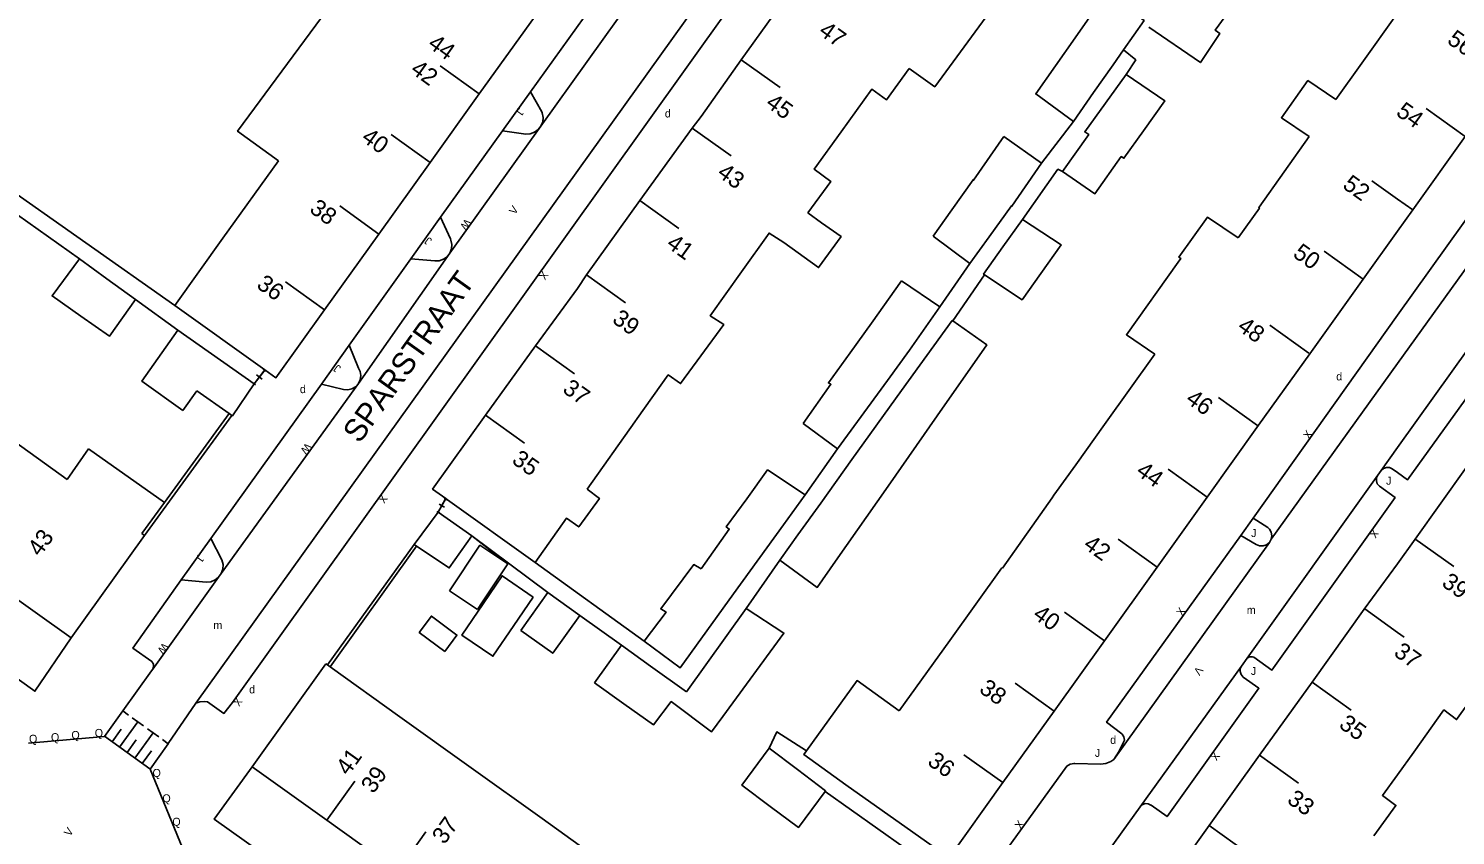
# Model space of a CAD drawing. Extents: x 134999 to 136502, y 457398 to 459002.
# Drawn here: x 135414.5 to 135503.6, y 457448.2 to 457498.6 of the extents above; entities that cross this region are included whole.
import ezdxf

# ---------------------------------------------------------------- set-up
doc = ezdxf.new("R2010")
doc.units = 0
for name, color, linetype in [('RI_DGTB_15', 7, 'Continuous'), ('RI_DGTB_23', 7, 'Continuous'), ('RI_DGTB_29', 7, 'Continuous'), ('RI_DGTB_30', 7, 'Continuous'), ('RI_DGTB_31', 7, 'Continuous'), ('RI_DGTB_35', 7, 'Continuous'), ('RI_DGTB_36', 7, 'Continuous'), ('RI_DGTB_37', 7, 'Continuous'), ('RI_DGTB_4', 7, 'Continuous'), ('RI_DGTB_43', 7, 'Continuous'), ('RI_DGTB_48', 7, 'Continuous'), ('RI_DGTB_5', 7, 'Continuous'), ('RI_DGTB_53', 7, 'Continuous'), ('RI_DGTB_54', 7, 'Continuous'), ('RI_DGTB_6', 7, 'Continuous')]:
    doc.layers.add(name, color=color, linetype=linetype)

msp = doc.modelspace()

# ---------------------------------------------------------------- linework, layer by layer
at = {"layer": 'RI_DGTB_15'}
for p, q in [((135459.001, 457496.658), (135461.441, 457494.913)), ((135442.64, 457494.517), (135440.202, 457496.264)), ((135504.228, 457491.852), (135501.788, 457493.597)), ((135439.569, 457490.229), (135437.131, 457491.976)), ((135455.93, 457492.383), (135458.37, 457490.638)), ((135500, 457487.937), (135498.402, 457489.08)), ((135436.357, 457485.745), (135433.935, 457487.513)), ((135452.672, 457487.848), (135455.112, 457486.103)), ((135500.945, 457487.267), (135500, 457487.937)), ((135497.85, 457482.939), (135495.41, 457484.685)), ((135449.335, 457483.202), (135451.775, 457481.457)), ((135432.978, 457481.028), (135430.54, 457482.775)), ((135494.459, 457478.309), (135492.019, 457480.055)), ((135446.151, 457478.77), (135448.591, 457477.025)), ((135491.259, 457473.796), (135488.819, 457475.542)), ((135443.034, 457474.431), (135445.474, 457472.686)), ((135488.113, 457469.317), (135485.673, 457471.063)), ((135484.978, 457464.931), (135482.538, 457466.677)), ((135501.079, 457466.713), (135503.522, 457464.972)), ((135481.696, 457460.341), (135479.193, 457462.132)), ((135497.957, 457462.329), (135500, 457460.862)), ((135500, 457460.862), (135500.412, 457460.56)), ((135478.547, 457455.936), (135476.107, 457457.682)), ((135494.658, 457457.756), (135497.095, 457456.006)), ((135475.354, 457451.47), (135472.914, 457453.216)), ((135491.382, 457453.187), (135493.819, 457451.437)), ((135433.115, 457449.117), (135434.86, 457451.558)), ((135437.555, 457445.942), (135439.3, 457448.383)), ((135488.229, 457448.789), (135490.666, 457447.039))]:
    msp.add_line(p, q, dxfattribs=at)
at = {"layer": 'RI_DGTB_23'}
msp.add_line((135428.572, 457476.401), (135429.243, 457477.27), dxfattribs=at)
at = {"layer": 'RI_DGTB_31'}
for p, q in [((135420.373, 457455.949), (135420.727, 457455.693)), ((135420.963, 457455.523), (135421.671, 457455.011)), ((135419.702, 457454.027), (135420.273, 457454.817)), ((135420.174, 457453.686), (135421.317, 457455.267)), ((135421.117, 457453.003), (135422.26, 457454.584)), ((135421.906, 457454.84), (135422.614, 457454.328)), ((135419.23, 457454.368), (135422.061, 457452.321)), ((135420.645, 457453.345), (135421.217, 457454.135)), ((135422.85, 457454.158), (135423.204, 457453.902)), ((135421.589, 457452.662), (135422.161, 457453.453))]:
    msp.add_line(p, q, dxfattribs=at)
at = {"layer": 'RI_DGTB_4'}
for p, q in [((135459.001, 457496.658), (135462.228, 457501.151)), ((135446.129, 457499.387), (135442.64, 457494.517)), ((135439.569, 457490.229), (135442.64, 457494.517)), ((135452.672, 457487.848), (135455.93, 457492.383)), ((135504.228, 457491.852), (135500.945, 457487.267)), ((135436.357, 457485.745), (135439.569, 457490.229)), ((135449.335, 457483.202), (135452.672, 457487.848)), ((135500.945, 457487.267), (135500, 457485.946)), ((135432.978, 457481.028), (135436.357, 457485.745)), ((135500, 457485.946), (135497.85, 457482.939)), ((135497.85, 457482.939), (135494.513, 457478.27)), ((135423.623, 457481.289), (135429.243, 457477.27)), ((135443.034, 457474.431), (135446.151, 457478.77)), ((135494.513, 457478.27), (135491.321, 457473.805)), ((135491.321, 457473.805), (135488.113, 457469.317)), ((135422.974, 457468.984), (135418.233, 457472.329)), ((135501.103, 457466.696), (135504.31, 457471.196)), ((135422.974, 457468.984), (135421.562, 457467.037)), ((135488.113, 457469.317), (135484.978, 457464.931)), ((135421.562, 457467.037), (135421.724, 457466.92)), ((135417.141, 457460.514), (135421.724, 457466.92)), ((135500, 457465.15), (135501.103, 457466.696)), ((135484.978, 457464.931), (135481.696, 457460.341)), ((135497.921, 457462.308), (135500, 457465.15)), ((135412.26, 457464.007), (135417.141, 457460.514)), ((135494.658, 457457.756), (135497.921, 457462.308)), ((135481.696, 457460.341), (135478.547, 457455.936)), ((135433.064, 457458.886), (135428.447, 457452.454)), ((135491.382, 457453.187), (135494.658, 457457.756)), ((135478.547, 457455.936), (135475.354, 457451.47)), ((135488.229, 457448.789), (135491.382, 457453.187)), ((135428.447, 457452.454), (135433.115, 457449.117)), ((135433.115, 457449.117), (135437.555, 457445.942)), ((135485.025, 457444.32), (135488.229, 457448.789))]:
    msp.add_line(p, q, dxfattribs=at)
for points in [[(135459.001, 457496.658), (135456.491, 457493.108), (135455.93, 457492.383)], [(135446.151, 457478.77), (135448.769, 457482.362), (135449.335, 457483.202)], [(135429.243, 457477.27), (135429.933, 457476.777), (135432.978, 457481.028)], [(135440.547, 457469.228), (135439.721, 457469.819), (135443.034, 457474.431)], [(135440.649, 457469.155), (135440.547, 457469.228)], [(135446.125, 457465.234), (135440.649, 457469.155)], [(135465.542, 457451.338), (135471.987, 457446.759)], [(135471.987, 457446.759), (135475.354, 457451.47)]]:
    msp.add_lwpolyline(points, dxfattribs=at)
at = {"layer": 'RI_DGTB_48'}
for p, q in [((135428.572, 457476.401), (135429.243, 457477.27)), ((135428.572, 457476.401), (135429.235, 457477.26)), ((135429.075, 457476.698), (135428.732, 457476.963)), ((135429.321, 457477.194), (135429.149, 457477.326)), ((135428.658, 457476.335), (135428.486, 457476.467)), ((135440.079, 457468.371), (135440.547, 457469.228)), ((135440.079, 457468.371), (135440.531, 457469.198)), ((135440.47, 457468.694), (135440.14, 457468.875)), ((135440.614, 457469.153), (135440.448, 457469.243)), ((135440.162, 457468.326), (135439.996, 457468.416))]:
    msp.add_line(p, q, dxfattribs=at)
at = {"layer": 'RI_DGTB_5'}
for p, q in [((135500, 457499.566), (135497.771, 457496.449)), ((135497.771, 457496.449), (135496.14, 457494.169)), ((135494.486, 457491.848), (135491.348, 457487.445)), ((135426.63, 457485.491), (135430.097, 457490.337)), ((135423.623, 457481.289), (135426.63, 457485.491)), ((135484.84, 457478.256), (135481.697, 457473.86)), ((135452.361, 457474.014), (135452.511, 457474.225)), ((135412.628, 457473.48), (135416.894, 457470.424)), ((135449.373, 457469.804), (135452.361, 457474.014)), ((135481.697, 457473.86), (135479.894, 457471.338)), ((135416.894, 457470.424), (135418.233, 457472.329)), ((135479.894, 457471.338), (135478.54, 457469.445)), ((135478.418, 457469.275), (135475.319, 457464.868)), ((135478.54, 457469.445), (135478.418, 457469.275)), ((135472.028, 457460.361), (135468.865, 457455.961)), ((135433.064, 457458.886), (135433.163, 457458.832)), ((135433.163, 457458.832), (135433.326, 457458.715)), ((135433.326, 457458.715), (135437.681, 457455.591)), ((135437.681, 457455.591), (135442.134, 457452.397)), ((135501.011, 457453.375), (135500, 457451.96)), ((135446.56, 457449.221), (135442.134, 457452.397)), ((135451.135, 457445.939), (135446.56, 457449.221))]:
    msp.add_line(p, q, dxfattribs=at)
for points in [[(135471.691, 457501.15), (135474.306, 457499.335), (135471.088, 457494.967), (135469.497, 457496.098)], [(135433.856, 457500.753), (135430.67, 457496.428)], [(135430.67, 457496.428), (135427.543, 457492.184), (135430.097, 457490.337)], [(135465.248, 457492.15), (135467.155, 457494.812), (135468.081, 457494.151), (135469.497, 457496.098)], [(135496.14, 457494.169), (135494.404, 457495.352), (135492.749, 457493.03), (135494.486, 457491.848)], [(135465.248, 457492.15), (135463.569, 457489.806), (135464.599, 457489.051), (135463.16, 457487.087)], [(135491.348, 457487.445), (135491.325, 457487.413), (135491.368, 457487.385), (135490.035, 457485.521)], [(135463.16, 457487.087), (135464.019, 457486.457)], [(135490.035, 457485.521), (135488.133, 457486.816), (135486.339, 457484.307), (135486.463, 457484.222), (135486.303, 457483.998)], [(135459.016, 457483.392), (135460.739, 457485.821), (135461.671, 457485.231)], [(135461.671, 457485.231), (135463.834, 457483.662), (135465.24, 457485.601), (135464.019, 457486.457)], [(135486.303, 457483.998), (135483.063, 457479.467), (135484.84, 457478.256)], [(135459.016, 457483.392), (135457.07, 457480.649), (135457.908, 457480.104), (135456.486, 457478.151)], [(135452.511, 457474.225), (135454.447, 457476.953), (135455.218, 457476.41), (135456.486, 457478.151)], [(135446.125, 457465.234), (135448.087, 457467.991), (135448.857, 457467.45), (135450.148, 457469.238), (135449.373, 457469.804)], [(135472.028, 457460.361), (135475.285, 457464.892), (135475.319, 457464.868)], [(135463.089, 457453.464), (135466.24, 457457.848), (135468.865, 457455.961)], [(135501.011, 457453.375), (135502.898, 457456.015), (135503.689, 457455.414), (135504.985, 457457.229)], [(135465.542, 457451.338), (135462.917, 457453.225), (135463.089, 457453.464)], [(135500, 457451.96), (135499.054, 457450.673), (135499.902, 457450.04), (135498.524, 457448.136)]]:
    msp.add_lwpolyline(points, dxfattribs=at)
at = {"layer": 'RI_DGTB_53'}
for p, q in [((135446.495, 457492.508), (135454.75, 457504.049)), ((135445.841, 457494.655), (135444.098, 457492.208)), ((135500, 457477.662), (135510.887, 457492.825)), ((135444.098, 457492.208), (135440.221, 457486.824)), ((135440.796, 457484.565), (135446.495, 457492.508)), ((135440.221, 457486.824), (135438.375, 457484.213)), ((135509.439, 457485.634), (135500, 457472.409)), ((135438.375, 457484.213), (135434.52, 457478.808)), ((135435.092, 457476.411), (135440.796, 457484.565)), ((135434.52, 457478.808), (135432.783, 457476.38)), ((135492.114, 457466.678), (135500, 457477.662)), ((135432.783, 457476.38), (135425.87, 457466.727)), ((135426.524, 457464.549), (135435.092, 457476.411)), ((135498.975, 457470.973), (135500, 457472.409)), ((135490.599, 457459.244), (135498.766, 457470.678)), ((135425.87, 457466.727), (135424.028, 457464.145)), ((135482.281, 457452.917), (135491.999, 457466.483)), ((135422.243, 457458.552), (135426.36, 457464.315)), ((135426.36, 457464.315), (135426.524, 457464.549)), ((135422.175, 457458.457), (135422.243, 457458.552)), ((135483.914, 457449.95), (135490.252, 457458.756))]:
    msp.add_line(p, q, dxfattribs=at)
for points in [[(135445.841, 457494.655), (135453.025, 457504.677), (135454.05, 457503.897), (135454.259, 457503.842), (135454.473, 457503.866), (135454.665, 457503.966), (135454.75, 457504.049)], [(135424.927, 457456.431), (135458.449, 457503.225)], [(135445.841, 457494.655), (135446.552, 457493.398), (135446.577, 457493.331), (135446.628, 457493.052), (135446.6, 457492.77), (135446.495, 457492.508)], [(135444.098, 457492.208), (135445.541, 457492.007), (135445.824, 457492.024), (135446.09, 457492.119), (135446.32, 457492.285), (135446.495, 457492.508)], [(135440.221, 457486.824), (135440.833, 457485.452), (135440.865, 457485.374), (135440.921, 457485.102), (135440.897, 457484.825), (135440.796, 457484.565)], [(135438.375, 457484.213), (135439.86, 457484.076), (135440.138, 457484.09), (135440.4, 457484.183), (135440.626, 457484.345), (135440.796, 457484.565)], [(135434.52, 457478.808), (135435.101, 457477.376), (135435.198, 457477.173), (135435.241, 457476.912), (135435.205, 457476.65), (135435.092, 457476.411)], [(135432.783, 457476.38), (135434.164, 457476.045), (135434.428, 457476.025), (135434.685, 457476.083), (135434.914, 457476.216), (135435.092, 457476.411)], [(135425.87, 457466.727), (135426.568, 457465.386), (135426.633, 457465.105), (135426.618, 457464.819), (135426.524, 457464.549)], [(135424.028, 457464.145), (135425.59, 457463.989), (135425.874, 457464.023), (135426.137, 457464.135), (135426.36, 457464.315)], [(135424.028, 457464.145), (135421, 457459.868), (135422.19, 457459.039), (135422.281, 457458.881), (135422.297, 457458.701), (135422.243, 457458.552)], [(135422.175, 457458.457), (135420.37, 457455.951)], [(135422.175, 457458.457), (135422.235, 457458.53), (135422.243, 457458.552)], [(135424.927, 457456.431), (135423.215, 457453.917), (135423.203, 457453.899)], [(135427.22, 457456.487), (135426.691, 457455.799), (135425.655, 457456.509), (135425.475, 457456.541), (135425.193, 457456.525), (135424.927, 457456.431)], [(135420.37, 457455.951), (135419.22, 457454.354)], [(135423.203, 457453.899), (135422.079, 457452.308)]]:
    msp.add_lwpolyline(points, dxfattribs=at)
at = {"layer": 'RI_DGTB_54'}
for p, q in [((135427.22, 457456.487), (135458.265, 457499.925)), ((135477.756, 457490.187), (135479.749, 457492.793)), ((135411.001, 457490.183), (135423.623, 457481.289)), ((135417.672, 457484.202), (135412.31, 457488)), ((135473.292, 457483.91), (135471.401, 457481.201)), ((135474.197, 457483.203), (135472.218, 457480.335)), ((135423.814, 457479.761), (135421.159, 457481.663)), ((135500, 457480.686), (135490.981, 457468.001)), ((135421.724, 457466.92), (135427.173, 457474.426)), ((135422.974, 457468.984), (135427.009, 457474.54)), ((135462.987, 457469.457), (135465.026, 457472.325)), ((135498.766, 457470.678), (135498.975, 457470.973)), ((135490.202, 457466.915), (135490.981, 457468.001)), ((135438.573, 457466.35), (135433.163, 457458.832)), ((135438.725, 457466.248), (135433.326, 457458.715)), ((135442.184, 457466.902), (135444.434, 457465.137)), ((135442.184, 457466.902), (135446.914, 457463.356)), ((135491.999, 457466.483), (135492.114, 457466.678)), ((135446.125, 457465.234), (135452.941, 457460.301)), ((135461.417, 457465.373), (135459.311, 457462.361)), ((135448.914, 457461.92), (135451.516, 457460.052)), ((135490.252, 457458.756), (135490.599, 457459.244)), ((135419.22, 457454.354), (135414.481, 457453.941)), ((135422.079, 457452.308), (135424.272, 457446.97)), ((135469.171, 457447.422), (135464.25, 457450.924))]:
    msp.add_line(p, q, dxfattribs=at)
for points in [[(135483.046, 457495.733), (135483.651, 457496.641), (135482.887, 457497.272)], [(135500, 457480.686), (135509.207, 457493.544), (135510.214, 457492.793), (135510.266, 457492.764), (135510.476, 457492.707), (135510.692, 457492.728), (135510.887, 457492.825)], [(135476.565, 457486.676), (135478.781, 457489.811), (135479.062, 457489.66)], [(135509.439, 457485.634), (135509.408, 457485.538), (135509.395, 457485.312), (135509.461, 457485.096), (135509.598, 457484.916), (135510.577, 457484.2), (135500.627, 457470.397), (135500, 457470.85)], [(135417.141, 457460.514), (135414.883, 457457.178), (135392.266, 457473.388), (135394.588, 457476.654)], [(135490.599, 457459.244), (135490.757, 457459.328), (135490.936, 457459.336), (135491.03, 457459.307), (135492.15, 457458.506), (135499.85, 457469.288), (135498.866, 457469.992), (135498.736, 457470.142), (135498.675, 457470.331), (135498.693, 457470.529), (135498.766, 457470.678)], [(135498.975, 457470.973), (135499.12, 457471.108), (135499.306, 457471.176), (135499.504, 457471.166), (135499.669, 457471.089), (135500, 457470.85)], [(135490.981, 457468.001), (135491.897, 457467.417), (135492.002, 457467.318), (135492.115, 457467.123), (135492.154, 457466.9), (135492.114, 457466.678)], [(135490.202, 457466.915), (135481.821, 457455.241), (135482.786, 457454.523), (135482.804, 457454.505), (135482.91, 457454.331), (135482.941, 457454.13), (135482.888, 457453.994), (135482.62, 457453.436), (135482.281, 457452.917)], [(135490.202, 457466.915), (135491.174, 457466.355), (135491.384, 457466.272), (135491.61, 457466.267), (135491.824, 457466.341), (135491.999, 457466.483)], [(135483.914, 457449.95), (135484.048, 457450.087), (135484.227, 457450.159), (135484.419, 457450.152), (135484.592, 457450.069), (135484.614, 457450.051), (135485.606, 457449.342), (135491.336, 457457.366), (135490.352, 457458.07), (135490.222, 457458.22), (135490.161, 457458.409), (135490.179, 457458.607), (135490.252, 457458.756)], [(135463.089, 457453.464), (135461.218, 457454.634), (135460.752, 457453.622)], [(135482.281, 457452.917), (135482.084, 457452.791), (135481.773, 457452.673), (135481.442, 457452.632), (135479.846, 457452.672), (135479.791, 457452.672), (135479.548, 457452.625), (135479.332, 457452.503), (135470.691, 457440.521), (135465.191, 457432.721), (135463.924, 457431.031)], [(135459.986, 457429.906), (135457.731, 457426.656), (135426.083, 457449.181), (135428.447, 457452.454)], [(135477.747, 457445.046), (135477.842, 457445.445), (135477.985, 457445.771), (135478.23, 457446.158), (135478.526, 457446.508), (135478.832, 457446.656), (135479.164, 457446.73), (135479.357, 457446.736), (135481.578, 457446.678), (135483.914, 457449.95)]]:
    msp.add_lwpolyline(points, dxfattribs=at)
at = {"layer": 'RI_DGTB_6'}
for p, q in [((135475.413, 457491.866), (135477.756, 457490.187)), ((135473.292, 457483.91), (135470.999, 457485.632)), ((135467.141, 457480.181), (135469.021, 457482.831)), ((135471.401, 457481.201), (135469.521, 457478.501)), ((135423.814, 457479.761), (135428.572, 457476.401)), ((135424.128, 457474.725), (135424.989, 457475.949)), ((135427.009, 457474.54), (135424.989, 457475.949)), ((135427.173, 457474.426), (135427.009, 457474.54)), ((135462.871, 457473.919), (135465.026, 457472.325)), ((135440.079, 457468.371), (135438.573, 457466.35)), ((135442.184, 457466.902), (135440.079, 457468.371)), ((135438.573, 457466.35), (135438.725, 457466.248)), ((135444.434, 457465.137), (135442.808, 457462.707)), ((135442.529, 457462.29), (135440.778, 457463.462)), ((135442.808, 457462.707), (135442.529, 457462.29)), ((135446.014, 457463.071), (135444.802, 457461.288)), ((135445.226, 457460.986), (135446.914, 457463.356)), ((135451.516, 457460.052), (135449.842, 457457.7))]:
    msp.add_line(p, q, dxfattribs=at)
for points in [[(135479.853, 457498.029), (135481.8, 457500.814), (135484.17, 457499.104), (135482.887, 457497.272)], [(135490.638, 457501.317), (135488.617, 457498.496), (135488.909, 457498.288), (135487.689, 457496.478), (135484.456, 457498.683)], [(135479.853, 457498.029), (135478.626, 457496.274)], [(135482.887, 457497.272), (135482.233, 457496.339)], [(135478.626, 457496.274), (135477.4, 457494.519), (135479.749, 457492.793)], [(135481.017, 457494.603), (135482.233, 457496.339)], [(135483.046, 457495.733), (135481.754, 457493.937)], [(135483.046, 457495.733), (135485.473, 457494.08), (135484.14, 457492.219)], [(135479.749, 457492.793), (135481.017, 457494.603)], [(135481.754, 457493.937), (135480.461, 457492.141), (135480.71, 457491.973), (135479.062, 457489.66)], [(135484.14, 457492.219), (135482.903, 457490.494), (135482.743, 457490.602), (135481.092, 457488.276), (135479.062, 457489.66)], [(135475.413, 457491.866), (135473.52, 457489.124), (135473.483, 457489.149), (135472.153, 457487.266)], [(135477.756, 457490.187), (135475.911, 457487.501), (135475.881, 457487.514), (135474.492, 457485.58)], [(135472.153, 457487.266), (135470.999, 457485.632)], [(135476.565, 457486.676), (135475.352, 457484.959)], [(135476.565, 457486.676), (135478.989, 457485.076), (135477.716, 457483.29)], [(135474.492, 457485.58), (135473.292, 457483.91)], [(135475.352, 457484.959), (135474.138, 457483.242), (135474.197, 457483.203)], [(135417.751, 457480.636), (135415.953, 457481.894), (135417.672, 457484.202)], [(135417.672, 457484.202), (135419.377, 457482.96)], [(135477.716, 457483.29), (135476.549, 457481.652), (135474.197, 457483.203)], [(135419.377, 457482.96), (135421.159, 457481.663)], [(135469.021, 457482.831), (135471.401, 457481.201)], [(135421.159, 457481.663), (135419.549, 457479.379), (135417.751, 457480.636)], [(135472.218, 457480.335), (135472.181, 457480.361), (135469.024, 457475.975)], [(135472.218, 457480.335), (135474.342, 457478.825), (135471.241, 457474.39)], [(135423.814, 457479.761), (135421.557, 457476.563), (135424.128, 457474.725)], [(135465.813, 457478.34), (135467.141, 457480.181)], [(135462.871, 457473.919), (135464.602, 457476.374), (135464.451, 457476.451), (135465.813, 457478.34)], [(135468.144, 457476.608), (135469.521, 457478.501)], [(135428.572, 457476.401), (135427.221, 457474.393), (135427.173, 457474.426)], [(135465.026, 457472.325), (135468.144, 457476.608)], [(135469.024, 457475.975), (135465.921, 457471.663)], [(135471.241, 457474.39), (135468.171, 457469.999)], [(135465.921, 457471.663), (135463.966, 457468.946), (135462.547, 457466.957)], [(135462.987, 457469.457), (135460.653, 457471.019), (135459.35, 457469.218)], [(135468.171, 457469.999), (135464.9, 457465.322)], [(135459.35, 457469.218), (135458.071, 457467.451), (135458.258, 457467.315), (135456.49, 457464.834)], [(135462.987, 457469.457), (135461.64, 457467.589)], [(135461.64, 457467.589), (135458.52, 457463.262)], [(135462.547, 457466.957), (135461.417, 457465.373)], [(135438.725, 457466.248), (135440.76, 457464.887), (135442.184, 457466.902)], [(135440.778, 457463.462), (135442.683, 457466.309), (135444.434, 457465.137)], [(135464.9, 457465.322), (135463.747, 457463.673), (135461.417, 457465.373)], [(135442.881, 457462.655), (135444.064, 457464.396), (135446.014, 457463.071)], [(135456.49, 457464.834), (135456.04, 457465.098), (135453.971, 457462.331), (135454.311, 457462.131), (135452.941, 457460.301)], [(135444.802, 457461.288), (135443.496, 457459.367), (135441.547, 457460.692), (135442.881, 457462.655)], [(135446.914, 457463.356), (135448.914, 457461.92)], [(135458.52, 457463.262), (135455.194, 457458.649), (135452.941, 457460.301)], [(135440.488, 457459.669), (135438.89, 457460.858), (135439.648, 457461.878), (135441.247, 457460.688), (135440.488, 457459.669)], [(135448.914, 457461.92), (135447.232, 457459.558), (135445.226, 457460.986)], [(135455.578, 457457.135), (135459.311, 457462.361)], [(135459.311, 457462.361), (135461.665, 457460.813), (135457.844, 457455.597)], [(135451.516, 457460.052), (135453.339, 457458.743)], [(135453.339, 457458.743), (135455.578, 457457.135)], [(135451.67, 457456.399), (135449.842, 457457.7)], [(135457.844, 457455.597), (135457.151, 457454.651), (135454.634, 457456.537), (135453.521, 457455.081), (135451.67, 457456.399)], [(135460.816, 457449.986), (135459.042, 457451.301), (135460.752, 457453.622)], [(135460.752, 457453.622), (135462.518, 457452.282)], [(135462.518, 457452.282), (135464.271, 457450.952), (135464.25, 457450.924)], [(135464.25, 457450.924), (135462.59, 457448.671), (135460.816, 457449.986)]]:
    msp.add_lwpolyline(points, dxfattribs=at)

# ---------------------------------------------------------------- texts
at = {"layer": 'RI_DGTB_29'}
for p in [(135454.233, 457493.046), (135496.172, 457476.611), (135431.437, 457475.816), (135428.266, 457457.045), (135482.052, 457453.891)]:
    msp.add_text('d', height=0.5, dxfattribs=at).set_placement(p)
at = {"layer": 'RI_DGTB_30'}
for s, height, rotation, p in [('V', 0.499, 54.45469, (135444.864, 457486.928)), ('W', 0.5, 234.38658, (135441.778, 457486.752)), ('X', 0.499, 234.49066, (135446.585, 457483.495)), ('X', 0.499, 54.51169, (135494.461, 457472.899)), ('W', 0.5, 232.31567, (135431.823, 457472.74)), ('X', 0.499, 234.49066, (135436.545, 457469.523)), ('X', 0.5, 234.47246, (135498.468, 457467.352)), ('X', 0.5, 56.68932, (135486.549, 457461.828)), ('W', 0.5, 232.31567, (135422.893, 457460.249)), ('V', 0.5, 234.47246, (135487.488, 457458.776)), ('X', 0.5, 234.45312, (135427.477, 457456.846)), ('X', 0.5, 234.47246, (135488.535, 457453.444)), ('X', 0.499, 54.20213, (135476.455, 457448.514)), ('V', 0.5, 54.94409, (135417.068, 457448.065))]:
    msp.add_text(s, height=height, rotation=rotation, dxfattribs=at).set_placement(p)
at = {"layer": 'RI_DGTB_31'}
for height, rotation, p in [(0.499, 234.49066, (135445.086, 457493.692)), (0.5, 144.71794, (135439.722, 457485.425)), (0.5, 144.43248, (135434.042, 457477.45)), (0.499, 234.49066, (135425.117, 457465.791))]:
    msp.add_text('J', height=height, rotation=rotation, dxfattribs=at).set_placement(p)
for s, p in [('J', (135499.283, 457470.09)), ('J', (135490.852, 457466.821)), ('J', (135490.84, 457458.199)), ('Q', (135414.514, 457453.962)), ('Q', (135415.884, 457454.059)), ('Q', (135417.162, 457454.196)), ('Q', (135418.62, 457454.325)), ('J', (135481.092, 457453.081)), ('Q', (135422.23, 457451.823)), ('Q', (135422.847, 457450.24)), ('Q', (135423.468, 457448.773))]:
    msp.add_text(s, height=0.5, dxfattribs=at).set_placement(p)
at = {"layer": 'RI_DGTB_35'}
for s, rotation, p in [('44', 324.382, (135439.36, 457497.486)), ('36', 324.382, (135428.666, 457482.446)), ('35', 324.4141, (135444.611, 457471.486)), ('43', 54.4074, (135415.198, 457465.543)), ('41', 54.4302, (135434.457, 457451.853)), ('36', 324.4235, (135470.572, 457452.642))]:
    msp.add_text(s, height=1.054, rotation=rotation, dxfattribs=at).set_placement(p)
at = {"layer": 'RI_DGTB_36'}
for s, rotation, p in [('47', 324.4141, (135463.779, 457498.284)), ('56', 324.4395, (135503.032, 457497.739)), ('42', 324.382, (135438.28, 457495.883)), ('45', 324.4141, (135460.464, 457493.783)), ('54', 324.4395, (135499.843, 457493.231)), ('40', 324.382, (135435.213, 457491.629)), ('43', 324.4141, (135457.435, 457489.423)), ('52', 324.4235, (135496.505, 457488.68)), ('38', 323.8758, (135431.969, 457487.181)), ('41', 324.4141, (135454.265, 457484.992)), ('50', 324.4235, (135493.399, 457484.387)), ('39', 324.4141, (135450.881, 457480.277)), ('48', 324.4235, (135489.929, 457479.809)), ('37', 324.4141, (135447.779, 457475.918)), ('46', 324.4235, (135486.703, 457475.282)), ('44', 324.4235, (135483.601, 457470.775)), ('42', 324.4235, (135480.31, 457466.184)), ('39', 324.5131, (135502.693, 457463.811)), ('40', 324.4235, (135477.153, 457461.812)), ('37', 324.5131, (135499.701, 457459.46)), ('38', 324.4235, (135473.8, 457457.169)), ('35', 324.3057, (135496.276, 457454.956)), ('39', 54.4369, (135436.027, 457450.73)), ('33', 324.3057, (135493.034, 457450.255)), ('37', 54.4369, (135440.465, 457447.553))]:
    msp.add_text(s, height=1.054, rotation=rotation, dxfattribs=at).set_placement(p)
at = {"layer": 'RI_DGTB_37'}
msp.add_text('SPARSTRAAT', height=1.4, rotation=54.45031, dxfattribs=at).set_placement((135435.159, 457472.611))
at = {"layer": 'RI_DGTB_43'}
for p in [(135490.582, 457462.008), (135426.029, 457461.062)]:
    msp.add_text('m', height=0.5, dxfattribs=at).set_placement(p)

doc.saveas('drawing.dxf')
